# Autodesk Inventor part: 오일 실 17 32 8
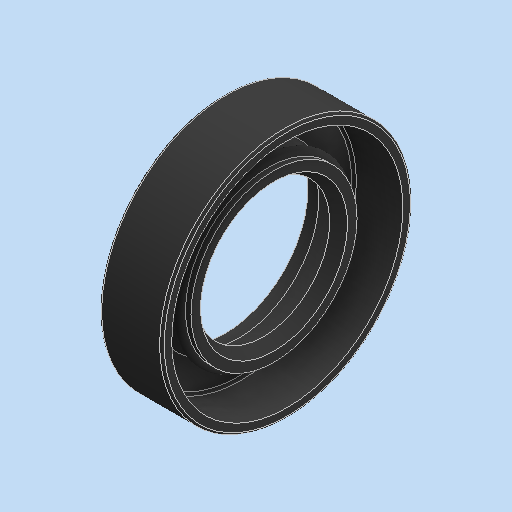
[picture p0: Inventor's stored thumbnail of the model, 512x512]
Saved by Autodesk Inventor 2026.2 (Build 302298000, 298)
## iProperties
Created: 2026-01
Part Number: 오일 실 17 32 8
Material: 고무
Description: 오일-실
Document SubType Name: Modeling
Designer: PC2-07
Density: 0.93 g/cm^3
Appearance: 기본값
Author: jhkim
Sending System: Autodesk Inventor 2026
Preprocessor: ST-DEVELOPER v20.1
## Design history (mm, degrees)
feature "Solid1"
node "솔리드1"
